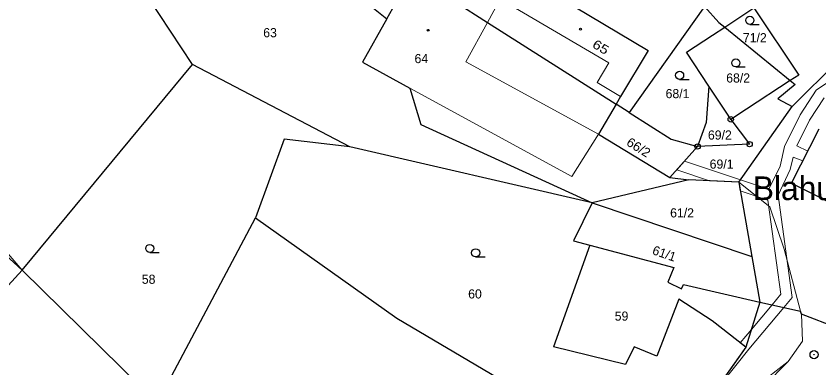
# Model space of a CAD drawing. Extents: x -504006 to -501322, y -1128098 to -1124665.
# Drawn here: x -502824.9 to -502675.9, y -1126597.3 to -1126531.9 of the extents above; entities that cross this region are included whole.
import ezdxf
from ezdxf.enums import TextEntityAlignment as Align

# ---------------------------------------------------------------- set-up
doc = ezdxf.new("R2010")
doc.units = 0
doc.header["$LTSCALE"] = 0.68
for name, color, linetype, lineweight in [('1', 7, 'Continuous', 25), ('13', 7, 'Continuous', 13), ('3', 7, 'Continuous', 25), ('4', 7, 'Continuous', 13), ('5', 7, 'Continuous', 25), ('7', 7, 'Continuous', 13), ('8', 7, 'Continuous', 25)]:
    doc.layers.add(name, color=color, linetype=linetype, lineweight=lineweight)
doc.layers.add('2', color=7, linetype='Continuous')

msp = doc.modelspace()

# ---------------------------------------------------------------- linework, layer by layer
at = {"layer": '1'}
for p, q in [((-502792.14, -1126540.91), (-502816.86, -1126503.09)), ((-502756.08, -1126532.45), (-502746.39, -1126515.1)), ((-502773.44, -1126518.37), (-502756.08, -1126532.45)), ((-502732.23, -1126523.58), (-502707.62, -1126538.32)), ((-502743.42, -1126529.26), (-502737.43, -1126533.08)), ((-502697.16, -1126530.12), (-502711.14, -1126549.85)), ((-502697.16, -1126530.12), (-502694.48, -1126533.09)), ((-502756.08, -1126532.45), (-502760.58, -1126540.5)), ((-502680.89, -1126548.73), (-502664.57, -1126532.42)), ((-502737.43, -1126533.08), (-502713.57, -1126548.3)), ((-502695.67, -1126535.43), (-502693.42, -1126533.96)), ((-502694.48, -1126533.09), (-502693.42, -1126533.96)), ((-502693.42, -1126533.96), (-502681.26, -1126543.91)), ((-502707.62, -1126538.32), (-502712.72, -1126546.86)), ((-502823.75, -1126579.14), (-502792.14, -1126540.91)), ((-502762.93, -1126556.2), (-502792.14, -1126540.91)), ((-502760.58, -1126540.5), (-502751.8, -1126545.29)), ((-502681.26, -1126543.91), (-502680.37, -1126544.64)), ((-502751.8, -1126545.29), (-502749.8, -1126552.08)), ((-502696.35, -1126544.93), (-502696.83, -1126551.68)), ((-502680.37, -1126544.64), (-502683.54, -1126547.27)), ((-502712.72, -1126546.86), (-502713.57, -1126548.3)), ((-502683.54, -1126547.27), (-502680.89, -1126548.73)), ((-502713.57, -1126548.3), (-502716.85, -1126553.83)), ((-502711.14, -1126549.85), (-502713.57, -1126548.3)), ((-502690.82, -1126562.8), (-502680.89, -1126548.73)), ((-502711.14, -1126549.85), (-502703.38, -1126554.8)), ((-502696.83, -1126551.68), (-502698.45, -1126556.15)), ((-502692.3, -1126551.1), (-502688.8, -1126555.71)), ((-502749.8, -1126552.08), (-502718.03, -1126566.59)), ((-502681.01, -1126562.98), (-502675.91, -1126552.87)), ((-502762.93, -1126556.2), (-502775.11, -1126554.81)), ((-502716.85, -1126553.83), (-502703.59, -1126561.93)), ((-502703.38, -1126554.8), (-502698.45, -1126556.15)), ((-502849.18, -1126555.55), (-502823.75, -1126579.14)), ((-502718.03, -1126566.59), (-502762.93, -1126556.2)), ((-502698.45, -1126556.15), (-502703.59, -1126561.93)), ((-502688.8, -1126555.71), (-502698.45, -1126556.15)), ((-502700.07, -1126562.31), (-502718.03, -1126566.59)), ((-502703.59, -1126561.93), (-502700.07, -1126562.31)), ((-502690.82, -1126562.8), (-502700.07, -1126562.31)), ((-502690.82, -1126562.8), (-502688.39, -1126576.57)), ((-502718.03, -1126566.59), (-502721.49, -1126573.65)), ((-502718.03, -1126566.59), (-502688.39, -1126576.57)), ((-502798.68, -1126603.73), (-502780.47, -1126569.42)), ((-502721.49, -1126573.65), (-502718.43, -1126574.47)), ((-502718.43, -1126574.47), (-502725.18, -1126593.37)), ((-502718.43, -1126574.47), (-502702.87, -1126578.62)), ((-502688.39, -1126576.57), (-502686.9, -1126585.04)), ((-502702.87, -1126578.62), (-502703.95, -1126581.33)), ((-502823.75, -1126579.14), (-502832.16, -1126588.37)), ((-502823.75, -1126579.14), (-502798.68, -1126603.73)), ((-502703.95, -1126581.33), (-502701.43, -1126582.57)), ((-502701.43, -1126582.57), (-502701.06, -1126581.8)), ((-502701.06, -1126581.8), (-502686.9, -1126585.04)), ((-502701.94, -1126584.5), (-502706.01, -1126595.09)), ((-502695.73, -1126588.53), (-502701.94, -1126584.5)), ((-502686.9, -1126585.04), (-502689.51, -1126593.45)), ((-502686.9, -1126585.04), (-502679.34, -1126586.77)), ((-502679.2, -1126587.28), (-502679.34, -1126586.77)), ((-502660.89, -1126594.42), (-502679.2, -1126587.28)), ((-502754.26, -1126588.07), (-502735.5, -1126599.1)), ((-502689.51, -1126593.45), (-502695.73, -1126588.53)), ((-502711.82, -1126596.62), (-502725.18, -1126593.37)), ((-502710.23, -1126593.39), (-502711.82, -1126596.62)), ((-502706.01, -1126595.09), (-502710.23, -1126593.39)), ((-502689.51, -1126593.45), (-502703.39, -1126613))]:
    msp.add_line(p, q, dxfattribs=at)
for points in [[(-502693.42, -1126533.96), (-502688, -1126530.4), (-502679.7, -1126542.9), (-502681.26, -1126543.91)], [(-502696.35, -1126544.93), (-502700.5, -1126538.6), (-502695.67, -1126535.43)], [(-502681.26, -1126543.91), (-502689.39, -1126549.21), (-502692.3, -1126551.1)], [(-502692.3, -1126551.1), (-502692.8, -1126550.34), (-502696.35, -1126544.93)], [(-502775.11, -1126554.81), (-502780.47, -1126569.42), (-502754.26, -1126588.07)], [(-502681.01, -1126562.98), (-502670.2, -1126568.43), (-502665.11, -1126558.27)]]:
    msp.add_lwpolyline(points, dxfattribs=at)
at = {"layer": '13'}
msp.add_lwpolyline([(-502664.63, -1126537.73), (-502676.45, -1126545.69), (-502679.44, -1126550.25), (-502682.31, -1126556.17), (-502683.16, -1126559.77), (-502685.22, -1126564.06), (-502690.48, -1126562.32), (-502700.87, -1126558.87), (-502702.32, -1126560.5), (-502696.25, -1126562.51), (-502690.82, -1126562.8), (-502690.54, -1126564.41), (-502685.41, -1126566.11), (-502682.99, -1126583.61), (-502684.63, -1126585.56), (-502688.48, -1126590.14), (-502689.51, -1126593.45), (-502696.43, -1126603.19), (-502688.95, -1126593.79), (-502682.44, -1126586.06), (-502680.89, -1126584.21), (-502683.52, -1126565.16), (-502681.26, -1126560.44), (-502680.71, -1126558.1), (-502678.92, -1126558.83), (-502677.99, -1126556.99), (-502680.02, -1126556.04), (-502677.7, -1126551.25), (-502674.99, -1126547.13)], dxfattribs=at)
msp.add_lwpolyline([(-502690.57, -1126592.62), (-502689.51, -1126593.45), (-502688.48, -1126590.14)], close=True, dxfattribs=at)
at = {"layer": '3'}
for p, q in [((-502688.763, -1126533.45), (-502687.013, -1126533.45)), ((-502691.353, -1126541.37), (-502689.603, -1126541.37)), ((-502701.783, -1126543.67), (-502700.033, -1126543.67)), ((-502800.053, -1126575.83), (-502798.303, -1126575.83)), ((-502739.613, -1126576.65), (-502737.863, -1126576.65))]:
    msp.add_line(p, q, dxfattribs=at)
for centre in [(-502688.7629, -1126532.6998), (-502691.3529, -1126540.6198), (-502701.7829, -1126542.9198), (-502800.0529, -1126575.0798), (-502739.6129, -1126575.8998)]:
    msp.add_circle(centre, 0.75, dxfattribs=at)
at = {"layer": '4'}
for p, q in [((-502735.04, -1126528.73), (-502737.43, -1126533.08)), ((-502714.9, -1126540.61), (-502735.04, -1126528.73)), ((-502737.43, -1126533.08), (-502741.43, -1126540.4)), ((-502741.43, -1126540.4), (-502716.85, -1126553.83)), ((-502717.1, -1126544.28), (-502714.9, -1126540.61)), ((-502712.72, -1126546.86), (-502717.1, -1126544.28)), ((-502721.77, -1126561.7), (-502751.8, -1126545.29)), ((-502716.85, -1126553.83), (-502721.77, -1126561.7)), ((-502843.37, -1126556.26), (-502823.75, -1126579.14)), ((-502690.82, -1126562.8), (-502685.03, -1126567.36)), ((-502685.03, -1126567.36), (-502682.4, -1126575.24)), ((-502682.4, -1126575.24), (-502679.34, -1126586.77)), ((-502678.97, -1126592.29), (-502679.2, -1126587.28)), ((-502681.67, -1126596.09), (-502678.97, -1126592.29)), ((-502703.39, -1126613), (-502681.67, -1126596.09)), ((-502681.67, -1126596.09), (-502695.8, -1126610.4))]:
    msp.add_line(p, q, dxfattribs=at)
at = {"layer": '5'}
for centre in [(-502720.1768, -1126534.3592), (-502748.4068, -1126534.5592)]:
    msp.add_circle(centre, 0.175, dxfattribs=at)
at = {"layer": '8'}
for centre, radius in [((-502692.3, -1126551.0999), 0.5), ((-502692.3, -1126551.0999), 0.0303), ((-502698.45, -1126556.1499), 0.5), ((-502698.45, -1126556.1499), 0.0303), ((-502688.8, -1126555.7099), 0.5), ((-502688.8, -1126555.7099), 0.0303), ((-502676.85, -1126594.8198), 0.75), ((-502676.85, -1126594.8198), 0.03)]:
    msp.add_circle(centre, radius, dxfattribs=at)

# ---------------------------------------------------------------- texts
at = {"layer": '2'}
for s, p in [('63', (-502777.749, -1126535.855)), ('71/2', (-502687.839, -1126536.785)), ('64', (-502749.689, -1126540.655)), ('68/2', (-502690.929, -1126544.265)), ('68/1', (-502702.169, -1126547.165)), ('69/2', (-502694.319, -1126554.865)), ('69/1', (-502693.999, -1126560.265)), ('61/2', (-502701.329, -1126569.325)), ('58', (-502800.269, -1126581.655)), ('60', (-502739.739, -1126584.385)), ('59', (-502712.559, -1126588.505))]:
    msp.add_text(s, height=1.7, dxfattribs=at).set_placement(p, align=Align.CENTER)
for s, rotation, width, p in [('65', 329, 1.2, (-502716.8358, -1126538.3981)), ('66/2', 328, 1.05, (-502709.8349, -1126557.0333))]:
    msp.add_text(s, height=1.7, rotation=rotation, dxfattribs=dict(at, width=width)).set_placement(p, align=Align.CENTER)
msp.add_text('61/1', height=1.7, rotation=341, dxfattribs=at).set_placement((-502704.8967, -1126576.8396), align=Align.CENTER)
at = {"layer": '7'}
msp.add_text('Blahutovice', height=4.4, dxfattribs=at).set_placement((-502673, -1126566.1), align=Align.CENTER)

doc.saveas('drawing.dxf')
